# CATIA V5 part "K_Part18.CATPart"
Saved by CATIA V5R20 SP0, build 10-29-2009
Part number: Part18
Bounding box of the stored display mesh (mm): x -24.003 to 24.003, y 50.224 to 71.824, z -753 to -733
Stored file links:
  G:\Khaled_CFAO_2011\SIL\SIL_GR2\ctanaphiko\Khaled\CAD_ThinkMOTION\K_Part18.CATPart
  G:\Khaled_CFAO_2011\SIL\SIL_GR2\ctanaphiko\CATIA\Squelette.CATPart
  G:\Khaled_CFAO_2011\SIL\SIL_GR2\ctanaphiko\CATIA\Conception_Tripod.CATProduct
  G:\Khaled_CFAO_2011\SIL\SIL_GR2\ctanaphiko\Khaled\CAD_ThinkMOTION\K_Leg_Level2.CATPart
  G:\Khaled_CFAO_2011\SIL\SIL_GR2\ctanaphiko\Khaled\CAD_ThinkMOTION\K_Part8.CATPart
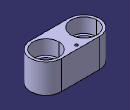
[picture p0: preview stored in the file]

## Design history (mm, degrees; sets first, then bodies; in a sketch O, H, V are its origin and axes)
Parameters
  Dia_Leg_Step3 = 15 mm
External parameters (linked from other documents)
  External.Dia_Leg_Step2 = 18 mm
AxisSystem1: origin (0, 0, 0), X (1, 0, 0), Y (0, 1, 0), Z (0, 0, 1)
Set1
  Plane1: linked copy from another document
  Point1: linked copy from another document
  Point2: linked copy from another document
  DatumCurve1 to DatumCurve4: linked copy from another document
  Sketch1, origin (0, 0, -68), H (1, 0, 0), V (0, 1, 0), geometry linked from another document
Body1 (main body)
  Sketch2 on Plane1, origin (0, 0, -743), H (1, 0, 0), V (0, 1, 0)
    construction line L1 (-13.2127, 61.024) -> (13.2127, 61.024)
    point P1 (-13.2127, 61.024)
    point P2 (13.2127, 61.024)
    line L2 (-13.2127, 71.824) -> (13.2127, 71.824)
    line L3 (13.2127, 50.224) -> (-13.2127, 50.224)
    arc A1 centre (13.2127, 61.024) radius 10.8 from (13.2127, 71.824) to (13.2127, 50.224) cw
    arc A2 centre (-13.2127, 61.024) radius 10.8 from (-13.2127, 50.224) to (-13.2127, 71.824) cw
    reference projected point E1 (-13.2127, 61.024) from Point1
    reference projected point E2 (13.2127, 61.024) from Point2
    projected circle E3 centre (13.2127, 61.024) radius 7.2 from edge of DatumCurve1
    projected circle E4 centre (-13.2127, 61.024) radius 7.2 from edge of DatumCurve2
    distance L1 L2 = 10.8 {= External.Dia_Leg_Step2/2 *1.2}
    horizontal: L1 H
    tangency: A1 L2, A2 L2, A1 L3, A2 L3
    coincidence: P1 E1, E2 P2
  Pad1: profile Sketch2, direction (0, 0, -1), length 10
  Sketch3 on Plane1, origin (0, 0, -743), H (1, 0, 0), V (0, 1, 0)
    construction line L1 (-13.2127, 61.024) -> (13.2127, 61.024)
    point P1 (-13.2127, 61.024)
    point P2 (13.2127, 61.024)
    line L2 (-13.2127, 71.824) -> (13.2127, 71.824)
    line L3 (13.2127, 50.224) -> (-13.2127, 50.224)
    arc A1 centre (13.2127, 61.024) radius 10.8 from (13.2127, 71.824) to (13.2127, 50.224) cw
    arc A2 centre (-13.2127, 61.024) radius 10.8 from (-13.2127, 50.224) to (-13.2127, 71.824) cw
    reference projected point E1 (-13.2127, 61.024) from Point1
    reference projected point E2 (13.2127, 61.024) from Point2
    projected circle E3 centre (-13.2127, 61.024) radius 9 from edge of DatumCurve3
    projected circle E4 centre (13.2127, 61.024) radius 9 from edge of DatumCurve4
    projected circle E5 centre (0, 69.024) radius 1 from Sketch1
    distance L1 L2 = 10.8 {= External.Dia_Leg_Step2/2 *1.2}
    horizontal: L1 H
    tangency: A1 L2, A2 L2, A1 L3, A2 L3
    coincidence: P1 E1, E2 P2
  Pad2: profile Sketch3, direction (0, 0, 1), length 10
